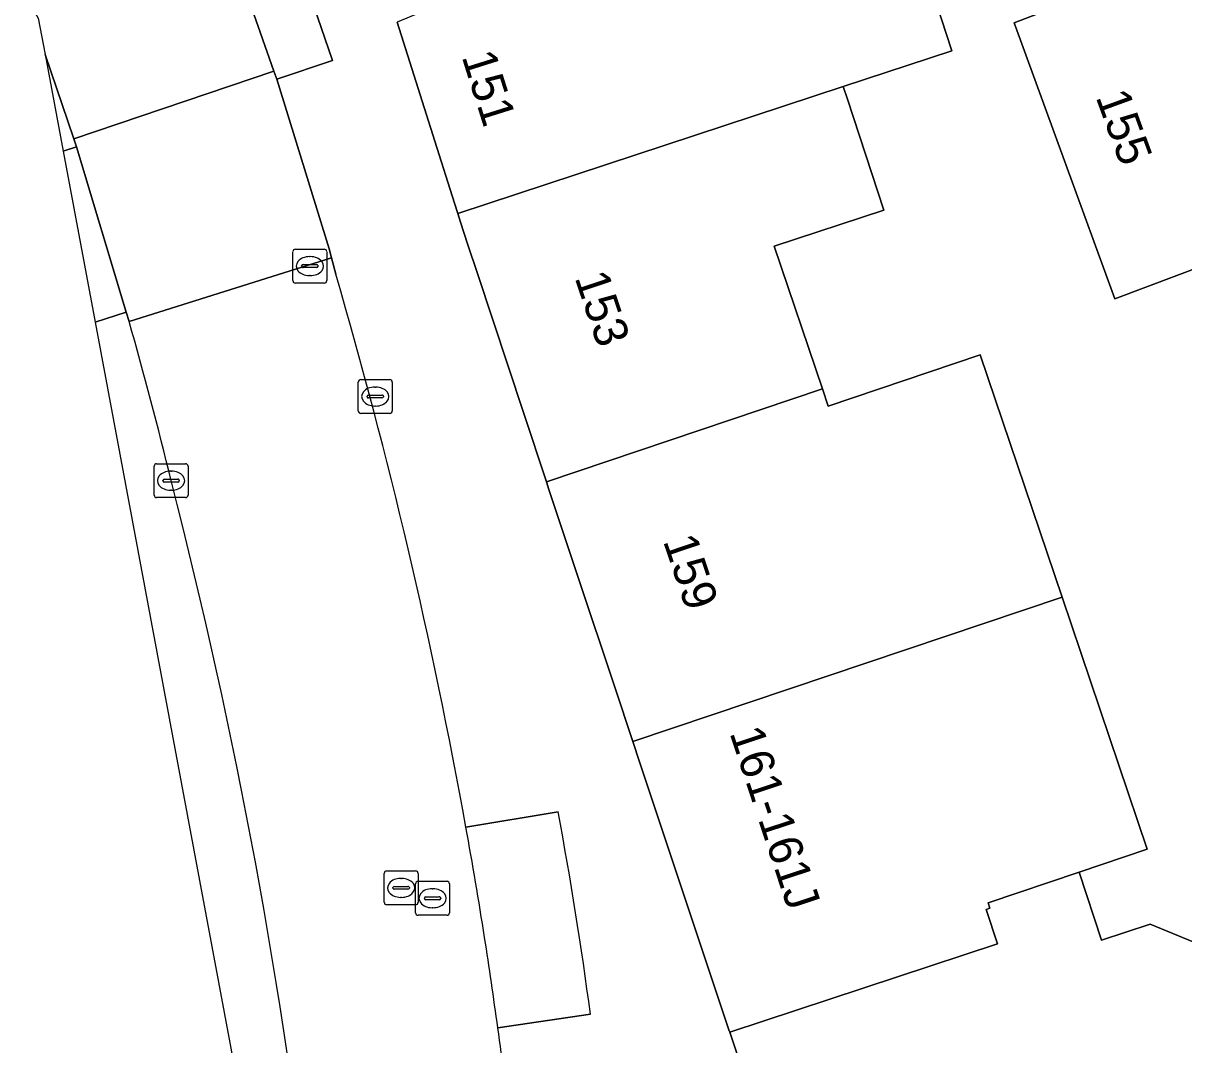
# Model space of a CAD drawing. Extents: x 161771 to 163125, y 382475 to 383179.
# Drawn here: x 161867.08 to 161901.28, y 382888.82 to 382918.93 of the extents above; entities that cross this region are included whole.
import ezdxf

# ---------------------------------------------------------------- set-up
doc = ezdxf.new("R2010")
doc.units = 0
for name, color, linetype in [('IMGEO_Berm_groen', 7, 'Continuous'), ('IMGEO_Berm_open', 7, 'Continuous'), ('IMGEO_Erf', 7, 'Continuous'), ('IMGEO_Groenvoorziening', 7, 'Continuous'), ('IMGEO_Kolk', 7, 'Continuous'), ('IMGEO_Pand', 7, 'Continuous'), ('IMGEO_Pand_nummerreeks', 7, 'Continuous'), ('IMGEO_Parkeervlak_open', 7, 'Continuous'), ('IMGEO_Rijbaan_lokaal_gesloten', 7, 'Continuous'), ('IMGEO_Rijbaan_lokaal_open', 7, 'Continuous'), ('IMGEO_Rioolput', 7, 'Continuous'), ('IMGEO_Voetpad_open', 7, 'Continuous')]:
    doc.layers.add(name, color=color, linetype=linetype)

msp = doc.modelspace()

# ---------------------------------------------------------------- linework, layer by layer
at = {"layer": 'IMGEO_Berm_groen'}
for points in [[(161867.723, 382918.011), (161868.256, 382915.158), (161868.649, 382915.29), (161868.568, 382915.527), (161867.723, 382918.011)], [(161870.198, 382910.139), (161870.118, 382910.413), (161869.198, 382910.119), (161875.913, 382874.211), (161876.365, 382859.64)]]:
    msp.add_lwpolyline(points, dxfattribs=at)
for centre, radius, start, end in [((161767.589, 382880.506), 106.802, 13.50506, 16.10829), ((161711.155, 382864.148), 165.518, 6.47393, 14.44921)]:
    msp.add_arc(centre, radius, start, end, dxfattribs=at)
at = {"layer": 'IMGEO_Berm_open'}
msp.add_lwpolyline([(161869.198, 382910.119), (161870.118, 382910.413), (161868.649, 382915.29), (161868.256, 382915.158), (161869.198, 382910.119)], dxfattribs=at)
at = {"layer": 'IMGEO_Erf'}
msp.add_lwpolyline([(161899.249, 382910.806), (161896.283, 382918.94), (161904.268, 382922.003), (161907.306, 382913.839)], close=True, dxfattribs=at)
msp.add_lwpolyline([(161893.38, 382921.376), (161894.448, 382918.118), (161891.246, 382917.063), (161891.366, 382916.696), (161892.439, 382913.423), (161889.208, 382912.363), (161890.632, 382908.151), (161890.802, 382907.648), (161895.282, 382909.161), (161897.696, 382902.016), (161900.204, 382894.592), (161898.194, 382893.913), (161898.849, 382891.905), (161900.292, 382892.376), (161903.701, 382890.975)], dxfattribs=at)
at = {"layer": 'IMGEO_Groenvoorziening'}
msp.add_lwpolyline([(161873.365, 382922.194), (161872.883, 382922.036), (161874.467, 382917.515), (161874.55, 382917.279), (161876.194, 382917.833), (161874.563, 382922.585)], close=True, dxfattribs=at)
at = {"layer": 'IMGEO_Kolk'}
for p, q in [((161876.953, 382907.502), (161876.953, 382908.354)), ((161877.028, 382908.428), (161877.88, 382908.428)), ((161877.954, 382908.354), (161877.954, 382907.502)), ((161877.255, 382907.971), (161877.653, 382907.971)), ((161877.441, 382908.208), (161877.466, 382908.208)), ((161877.212, 382907.922), (161877.212, 382907.934)), ((161877.65, 382907.885), (161877.252, 382907.885)), ((161877.464, 382907.648), (161877.439, 382907.648)), ((161877.696, 382907.934), (161877.696, 382907.922)), ((161877.88, 382907.428), (161877.028, 382907.428)), ((161871.012, 382905.948), (161871.864, 382905.948)), ((161870.937, 382905.022), (161870.937, 382905.874)), ((161871.425, 382905.728), (161871.45, 382905.728)), ((161871.938, 382905.874), (161871.938, 382905.022)), ((161871.196, 382905.442), (161871.196, 382905.454)), ((161871.634, 382905.405), (161871.236, 382905.405)), ((161871.239, 382905.491), (161871.637, 382905.491)), ((161871.68, 382905.454), (161871.68, 382905.442)), ((161871.864, 382904.948), (161871.012, 382904.948)), ((161871.448, 382905.168), (161871.423, 382905.168)), ((161877.791, 382893.948), (161878.643, 382893.948)), ((161877.716, 382893.022), (161877.716, 382893.874)), ((161878.204, 382893.728), (161878.229, 382893.728)), ((161878.716, 382893.642), (161879.568, 382893.642)), ((161878.717, 382893.874), (161878.717, 382893.022)), ((161877.975, 382893.442), (161877.975, 382893.454)), ((161878.413, 382893.405), (161878.015, 382893.405)), ((161878.018, 382893.491), (161878.416, 382893.491)), ((161878.459, 382893.454), (161878.459, 382893.442)), ((161878.641, 382892.716), (161878.641, 382893.568)), ((161879.129, 382893.422), (161879.154, 382893.422)), ((161879.642, 382893.568), (161879.642, 382892.716)), ((161878.643, 382892.948), (161877.791, 382892.948)), ((161878.227, 382893.168), (161878.202, 382893.168)), ((161878.9, 382893.136), (161878.9, 382893.148)), ((161879.338, 382893.099), (161878.94, 382893.099)), ((161878.943, 382893.185), (161879.341, 382893.185)), ((161879.384, 382893.148), (161879.384, 382893.136)), ((161879.568, 382892.642), (161878.716, 382892.642)), ((161879.152, 382892.862), (161879.127, 382892.862))]:
    msp.add_line(p, q, dxfattribs=at)
for points in [[(161876.953, 382907.502), (161876.953, 382908.354)], [(161877.028, 382908.428), (161877.88, 382908.428)], [(161877.954, 382908.354), (161877.954, 382907.502)], [(161877.88, 382907.428), (161877.028, 382907.428)], [(161871.012, 382905.948), (161871.864, 382905.948)], [(161870.937, 382905.022), (161870.937, 382905.874)], [(161871.938, 382905.874), (161871.938, 382905.022)], [(161871.864, 382904.948), (161871.012, 382904.948)], [(161877.791, 382893.948), (161878.643, 382893.948)], [(161877.716, 382893.022), (161877.716, 382893.874)], [(161878.716, 382893.642), (161879.568, 382893.642)], [(161878.717, 382893.874), (161878.717, 382893.022)], [(161878.641, 382892.716), (161878.641, 382893.568)], [(161879.642, 382893.568), (161879.642, 382892.716)], [(161878.643, 382892.948), (161877.791, 382892.948)], [(161879.568, 382892.642), (161878.716, 382892.642)]]:
    msp.add_lwpolyline(points, dxfattribs=at)
for centre, radius, start, end in [((161877.03, 382908.352), 0.0765, 91.552, 178.448), ((161877.03, 382908.352), 0.0765, 91.552, 178.448), ((161877.878, 382908.352), 0.0765, 1.552, 88.448), ((161877.878, 382908.352), 0.0765, 1.552, 88.448), ((161877.252, 382907.931), 0.0403, 85.8775, 175.7526), ((161877.657, 382907.933), 0.0386, 1.7309, 96.639), ((161877.249, 382907.921), 0.0366, 178.938, 274.7102), ((161877.653, 382907.928), 0.043, 264.8664, 352.4533), ((161877.03, 382907.504), 0.0765, 181.552, 268.448), ((161877.03, 382907.504), 0.0765, 181.552, 268.448), ((161877.878, 382907.504), 0.0765, 271.552, 358.448), ((161877.878, 382907.504), 0.0765, 271.552, 358.448), ((161871.014, 382905.872), 0.0765, 91.552, 178.448), ((161871.014, 382905.872), 0.0765, 91.552, 178.448), ((161871.862, 382905.872), 0.0765, 1.552, 88.448), ((161871.862, 382905.872), 0.0765, 1.552, 88.448), ((161871.236, 382905.451), 0.0403, 85.8775, 175.7526), ((161871.233, 382905.441), 0.0366, 178.938, 274.7102), ((161871.637, 382905.448), 0.043, 264.8664, 352.4533), ((161871.641, 382905.453), 0.0386, 1.7309, 96.639), ((161871.014, 382905.024), 0.0765, 181.552, 268.448), ((161871.014, 382905.024), 0.0765, 181.552, 268.448), ((161871.862, 382905.024), 0.0765, 271.552, 358.448), ((161871.862, 382905.024), 0.0765, 271.552, 358.448), ((161877.793, 382893.872), 0.0765, 91.552, 178.448), ((161877.793, 382893.872), 0.0765, 91.552, 178.448), ((161878.641, 382893.872), 0.0765, 1.552, 88.448), ((161878.641, 382893.872), 0.0765, 1.552, 88.448), ((161878.718, 382893.566), 0.0765, 91.552, 178.448), ((161878.718, 382893.566), 0.0765, 91.552, 178.448), ((161879.566, 382893.566), 0.0765, 1.552, 88.448), ((161879.566, 382893.566), 0.0765, 1.552, 88.448), ((161878.015, 382893.451), 0.0403, 85.8775, 175.7526), ((161878.012, 382893.441), 0.0366, 178.938, 274.7102), ((161878.416, 382893.448), 0.043, 264.8664, 352.4533), ((161878.42, 382893.453), 0.0386, 1.7309, 96.639), ((161877.793, 382893.024), 0.0765, 181.552, 268.448), ((161877.793, 382893.024), 0.0765, 181.552, 268.448), ((161878.641, 382893.024), 0.0765, 271.552, 358.448), ((161878.641, 382893.024), 0.0765, 271.552, 358.448), ((161878.94, 382893.145), 0.0403, 85.8775, 175.7526), ((161878.937, 382893.135), 0.0366, 178.938, 274.7102), ((161879.341, 382893.142), 0.043, 264.8664, 352.4533), ((161879.345, 382893.147), 0.0386, 1.7309, 96.639), ((161878.718, 382892.718), 0.0765, 181.552, 268.448), ((161878.718, 382892.718), 0.0765, 181.552, 268.448), ((161879.566, 382892.718), 0.0765, 271.552, 358.448), ((161879.566, 382892.718), 0.0765, 271.552, 358.448)]:
    msp.add_arc(centre, radius, start, end, dxfattribs=at)
for centre, major_axis, ratio, start_param, end_param in [((161877.44, 382907.928), (-0.387, 0.002), 0.722429, 4.712389, 7.853982), ((161877.465, 382907.928), (-0.39, 0.002), 0.717154, 1.570796, 4.712389), ((161871.424, 382905.448), (-0.387, 0.002), 0.722429, 4.712389, 7.853982), ((161871.449, 382905.448), (-0.39, 0.002), 0.717154, 1.570796, 4.712389), ((161878.203, 382893.448), (-0.387, 0.002), 0.722429, 4.712389, 7.853982), ((161878.228, 382893.448), (-0.39, 0.002), 0.717154, 1.570796, 4.712389), ((161879.128, 382893.142), (-0.387, 0.002), 0.722429, 4.712389, 7.853982), ((161879.153, 382893.142), (-0.39, 0.002), 0.717154, 1.570796, 4.712389)]:
    msp.add_ellipse(centre, major_axis=major_axis, ratio=ratio, start_param=start_param, end_param=end_param, dxfattribs=at)
at = {"layer": 'IMGEO_Pand'}
for points in [[(161894.448, 382918.118), (161893.38, 382921.376), (161888.944, 382919.922), (161888.832, 382920.262), (161888.039, 382922.681), (161887.918, 382923.05), (161878.103, 382918.961), (161879.208, 382915.457), (161879.786, 382913.625), (161879.883, 382913.317), (161891.246, 382917.063)], [(161904.268, 382922.003), (161896.283, 382918.94), (161899.249, 382910.806), (161907.306, 382913.839)], [(161892.439, 382913.423), (161891.366, 382916.696), (161891.246, 382917.063), (161879.883, 382913.317), (161879.962, 382913.065), (161880.174, 382912.426), (161880.463, 382911.552), (161881.82, 382907.454), (161882.496, 382905.414), (161890.632, 382908.151), (161889.208, 382912.363)], [(161895.282, 382909.161), (161890.802, 382907.648), (161890.632, 382908.151), (161882.496, 382905.414), (161882.573, 382905.183), (161882.786, 382904.541), (161883.433, 382902.597), (161884.51, 382899.362), (161885.042, 382897.761), (161897.696, 382902.016)], [(161898.194, 382893.913), (161900.204, 382894.592), (161897.696, 382902.016), (161885.042, 382897.761), (161885.242, 382897.159), (161886.956, 382892.009), (161887.027, 382891.798), (161887.669, 382889.881), (161887.877, 382889.261), (161887.898, 382889.199), (161895.789, 382891.8), (161895.456, 382892.809), (161895.568, 382892.848), (161895.514, 382893.008)], [(161904.135, 382889.963), (161904.042, 382889.933), (161903.701, 382890.975), (161900.292, 382892.376), (161898.849, 382891.905), (161898.194, 382893.913), (161895.514, 382893.008), (161895.568, 382892.848), (161895.456, 382892.809), (161895.789, 382891.8), (161887.898, 382889.199), (161888.885, 382886.256), (161889.229, 382885.233), (161890.343, 382881.911), (161890.362, 382881.855), (161898.115, 382884.744), (161897.858, 382885.524), (161902.213, 382886.96), (161902.272, 382886.78), (161902.306, 382886.792), (161904.769, 382887.646), (161904.921, 382887.699)]]:
    msp.add_lwpolyline(points, close=True, dxfattribs=at)
at = {"layer": 'IMGEO_Parkeervlak_open'}
for points in [[(161882.842, 382895.693), (161880.126, 382895.234)], [(161881.065, 382889.324), (161883.793, 382889.727)]]:
    msp.add_lwpolyline(points, dxfattribs=at)
for centre, radius, start, end in [((161771.387, 382874.868), 113.384, 7.53034, 10.58354), ((161714.558, 382865.511), 168.215, 9.05612, 10.17752), ((161712.527, 382866.074), 170.134, 7.85434, 8.76101)]:
    msp.add_arc(centre, radius, start, end, dxfattribs=at)
at = {"layer": 'IMGEO_Rijbaan_lokaal_gesloten'}
for points in [[(161867.723, 382918.011), (161868.568, 382915.527), (161874.467, 382917.515), (161872.883, 382922.036)], [(161867.08, 382919.9), (161867.113, 382919.802), (161867.523, 382919.079), (161867.723, 382918.011)], [(161876.29, 382911.535), (161876.167, 382912.02), (161870.198, 382910.139)]]:
    msp.add_lwpolyline(points, dxfattribs=at)
for centre, radius, start, end in [((161724.025, 382867.102), 158.615, 10.2161, 16.26807), ((161767.589, 382880.506), 106.802, 13.50506, 16.10829), ((161711.155, 382864.148), 165.518, 6.47393, 14.44921), ((161714.558, 382865.511), 168.215, 9.05612, 10.17752), ((161712.527, 382866.074), 170.134, 7.85434, 8.76101), ((161749.04, 382870.734), 133.327, 7.37944, 8.01474)]:
    msp.add_arc(centre, radius, start, end, dxfattribs=at)
at = {"layer": 'IMGEO_Rijbaan_lokaal_open'}
msp.add_lwpolyline([(161874.55, 382917.279), (161874.467, 382917.515), (161868.568, 382915.527), (161868.649, 382915.29), (161870.118, 382910.413), (161870.198, 382910.139), (161876.167, 382912.02), (161876.099, 382912.276)], close=True, dxfattribs=at)
at = {"layer": 'IMGEO_Rioolput'}
for p, q in [((161875.026, 382911.345), (161875.026, 382912.197)), ((161875.101, 382912.271), (161875.953, 382912.271)), ((161876.027, 382912.197), (161876.027, 382911.345)), ((161875.285, 382911.765), (161875.285, 382911.777)), ((161875.723, 382911.728), (161875.325, 382911.728)), ((161875.328, 382911.814), (161875.726, 382911.814)), ((161875.514, 382912.051), (161875.539, 382912.051)), ((161875.769, 382911.777), (161875.769, 382911.765)), ((161875.537, 382911.491), (161875.512, 382911.491)), ((161875.953, 382911.271), (161875.101, 382911.271))]:
    msp.add_line(p, q, dxfattribs=at)
for points in [[(161875.026, 382911.345), (161875.026, 382912.197)], [(161875.101, 382912.271), (161875.953, 382912.271)], [(161876.027, 382912.197), (161876.027, 382911.345)], [(161875.953, 382911.271), (161875.101, 382911.271)]]:
    msp.add_lwpolyline(points, dxfattribs=at)
for centre, radius, start, end in [((161875.103, 382912.195), 0.0765, 91.552, 178.448), ((161875.103, 382912.195), 0.0765, 91.552, 178.448), ((161875.951, 382912.195), 0.0765, 1.552, 88.448), ((161875.951, 382912.195), 0.0765, 1.552, 88.448), ((161875.325, 382911.774), 0.0403, 85.8775, 175.7526), ((161875.322, 382911.764), 0.0366, 178.938, 274.7102), ((161875.726, 382911.771), 0.043, 264.8664, 352.4533), ((161875.73, 382911.776), 0.0386, 1.7309, 96.639), ((161875.103, 382911.347), 0.0765, 181.552, 268.448), ((161875.103, 382911.347), 0.0765, 181.552, 268.448), ((161875.951, 382911.347), 0.0765, 271.552, 358.448), ((161875.951, 382911.347), 0.0765, 271.552, 358.448)]:
    msp.add_arc(centre, radius, start, end, dxfattribs=at)
for centre, major_axis, ratio, start_param, end_param in [((161875.513, 382911.771), (-0.387, 0.002), 0.722429, 4.712389, 7.853982), ((161875.538, 382911.771), (-0.39, 0.002), 0.717154, 1.570796, 4.712389)]:
    msp.add_ellipse(centre, major_axis=major_axis, ratio=ratio, start_param=start_param, end_param=end_param, dxfattribs=at)
at = {"layer": 'IMGEO_Voetpad_open'}
for points in [[(161873.365, 382922.194), (161874.563, 382922.585), (161876.194, 382917.833), (161874.55, 382917.279), (161876.099, 382912.276), (161876.167, 382912.02), (161876.29, 382911.535)], [(161888.885, 382886.256), (161887.898, 382889.199), (161887.877, 382889.261), (161887.669, 382889.881), (161887.027, 382891.798), (161886.956, 382892.009), (161885.242, 382897.159), (161885.042, 382897.761), (161884.51, 382899.362), (161883.433, 382902.597), (161882.786, 382904.541), (161882.573, 382905.183), (161882.496, 382905.414), (161881.82, 382907.454), (161880.463, 382911.552), (161880.174, 382912.426), (161879.962, 382913.065), (161879.883, 382913.317), (161879.786, 382913.625), (161879.208, 382915.457), (161878.103, 382918.961)], [(161880.126, 382895.234), (161882.842, 382895.693)], [(161883.793, 382889.727), (161881.065, 382889.324)]]:
    msp.add_lwpolyline(points, dxfattribs=at)
for centre, radius, start, end in [((161724.025, 382867.102), 158.615, 10.2161, 16.26807), ((161771.387, 382874.868), 113.384, 7.53034, 10.58354), ((161749.04, 382870.734), 133.327, 7.37944, 8.01474)]:
    msp.add_arc(centre, radius, start, end, dxfattribs=at)

# ---------------------------------------------------------------- texts
at = {"layer": 'IMGEO_Pand_nummerreeks'}
for s, rotation, p in [('151', 287.5037, (161879.995, 382917.949)), ('155', 290.0361, (161898.674, 382916.76)), ('153', 288.5235, (161883.324, 382911.435)), ('159', 288.5808, (161885.928, 382903.672)), ('161-161J', 288.2886, (161887.887, 382898.019))]:
    msp.add_text(s, height=1, rotation=rotation, dxfattribs=at).set_placement(p)

doc.saveas('drawing.dxf')
